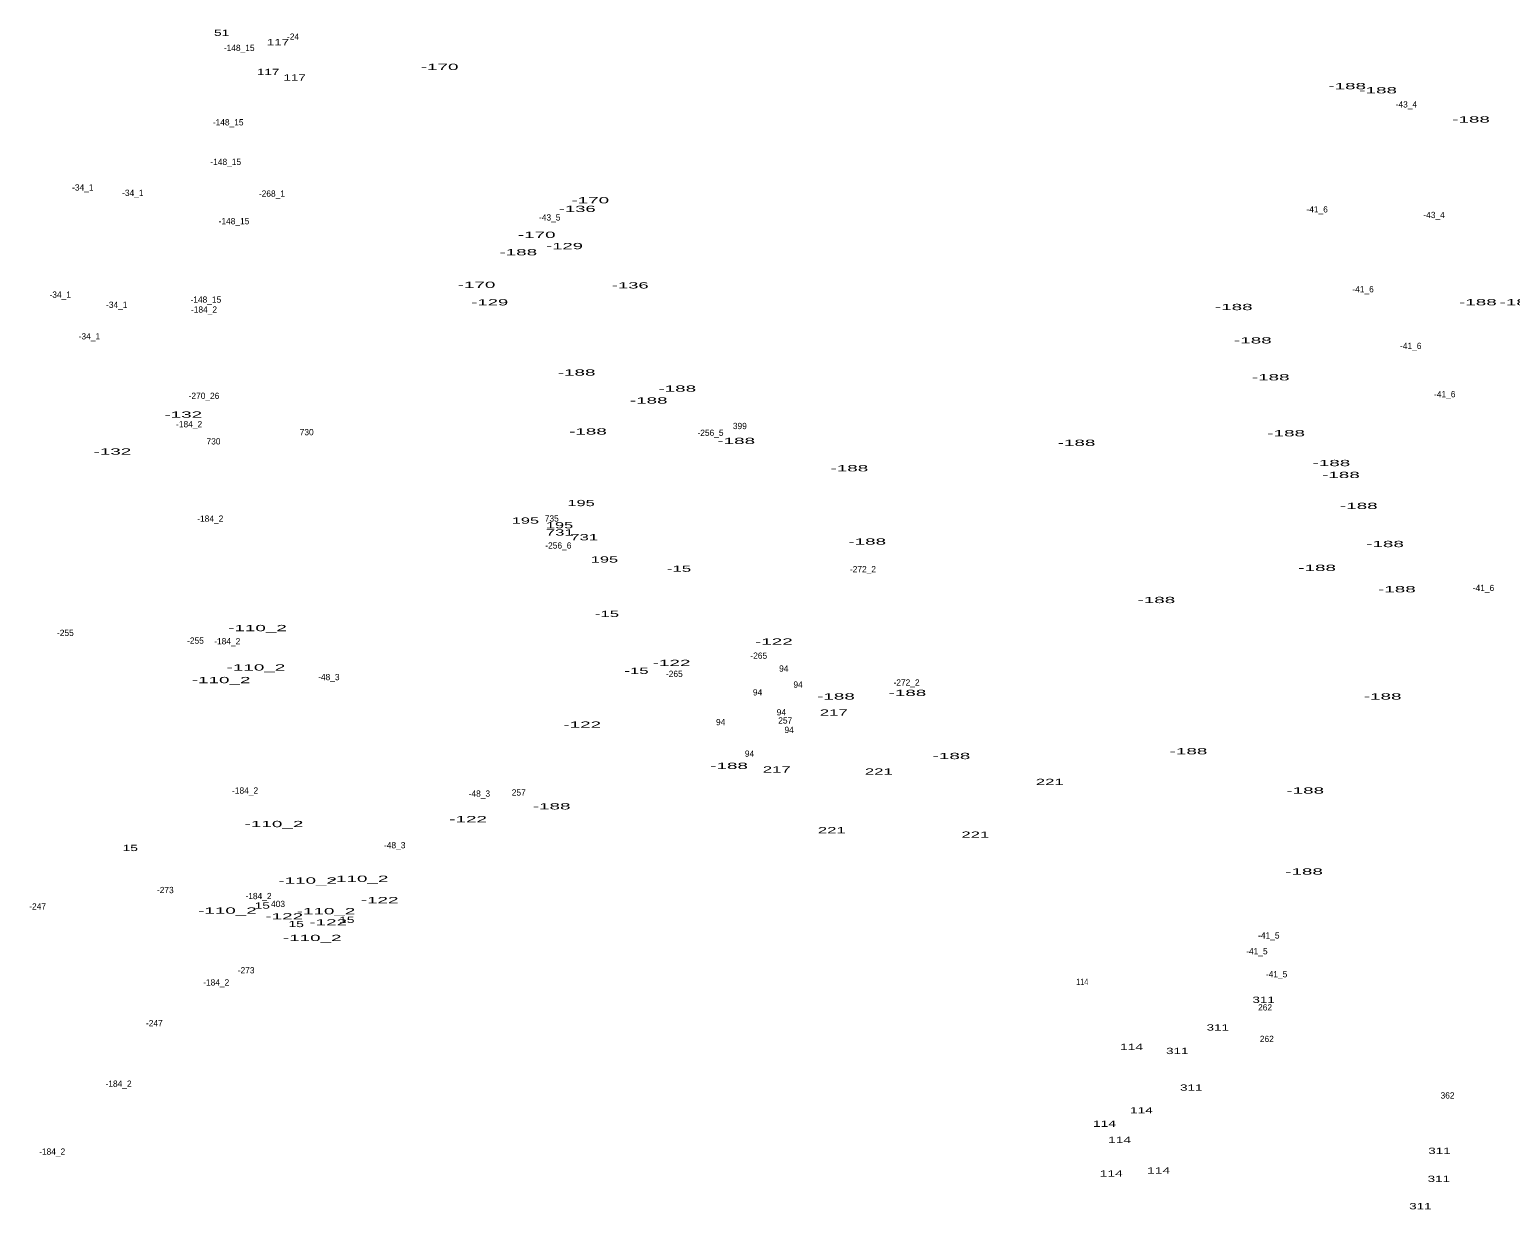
# Model space of a CAD drawing. Extents: x -658595 to -655205, y -1004347 to -1000147.
# Drawn here: x -657379 to -656433, y -1003735 to -1002981 of the extents above; entities that cross this region are included whole.
import ezdxf
from ezdxf.enums import TextEntityAlignment as Align

# ---------------------------------------------------------------- set-up
doc = ezdxf.new("R2010")
doc.units = 0
doc.header["$LTSCALE"] = 1.6
doc.layers.add('24', color=7, linetype='Continuous')

msp = doc.modelspace()

# ---------------------------------------------------------------- texts
at = {"layer": '24'}
for s, width, p in [('51', 1.65, (-657255.897, -1002984.88)), ('117', 1.6, (-657219.939, -1002990.92)), ('117', 1.6, (-657226.219, -1003009.94)), ('117', 1.6, (-657209.289, -1003013.46)), ('-170', 2.25, (-657116.701, -1003006.7)), ('-188', 2.25, (-656536.991, -1003018.98)), ('-188', 2.25, (-656517.211, -1003021.64)), ('-188', 2.25, (-656457.881, -1003040.28)), ('-136', 2.2, (-657028.795, -1003097.41)), ('-170', 2.25, (-657020.471, -1003091.93)), ('-170', 2.25, (-657054.701, -1003114)), ('-188', 2.25, (-657066.451, -1003125.14)), ('-129', 2.2, (-657036.925, -1003121.19)), ('-170', 2.25, (-657093.121, -1003145.96)), ('-136', 2.2, (-656994.945, -1003146.3)), ('-129', 2.2, (-657084.655, -1003157.14)), ('-188', 2.25, (-656609.451, -1003160.13)), ('-188', 2.25, (-656453.501, -1003157.09)), ('-188', 2.25, (-656427.631, -1003157.09)), ('-188', 2.25, (-656597.271, -1003181.44)), ('-188', 2.25, (-657029.181, -1003201.98)), ('-188', 2.25, (-656964.901, -1003212.25)), ('-188', 2.25, (-656585.861, -1003205.03)), ('-188', 2.25, (-656983.151, -1003219.86)), ('-132', 2.25, (-657280.441, -1003228.87)), ('-188', 2.25, (-657021.951, -1003239.65)), ('-188', 2.25, (-656575.971, -1003240.8)), ('-188', 2.25, (-656927.241, -1003245.69)), ('-188', 2.25, (-656709.861, -1003246.89)), ('-132', 2.25, (-657325.701, -1003252.46)), ('-188', 2.25, (-656547.071, -1003259.83)), ('-188', 2.25, (-656854.971, -1003263.19)), ('-188', 2.25, (-656540.981, -1003267.44)), ('195', 1.95, (-657026.323, -1003285.39)), ('-188', 2.25, (-656529.571, -1003287.22)), ('195', 1.95, (-657061.893, -1003296.61)), ('731', 2, (-657039.943, -1003304.19)), ('195', 1.95, (-657040.113, -1003299.56)), ('731', 2, (-657024.353, -1003307.24)), ('-188', 2.25, (-656843.561, -1003309.99)), ('-188', 2.25, (-656512.831, -1003311.57)), ('195', 1.95, (-657011.403, -1003321.44)), ('-15', 2, (-656963.771, -1003327.35)), ('-188', 2.25, (-656556.191, -1003326.79)), ('-188', 2.25, (-656505.231, -1003340.49)), ('-188', 2.25, (-656658.891, -1003347.34)), ('-15', 2, (-657009.791, -1003356.26)), ('-110_2', 2.25, (-657233.034, -1003365.28)), ('-122', 2.25, (-656903.171, -1003373.92)), ('-110_2', 2.25, (-657233.994, -1003390.44)), ('-122', 2.25, (-656968.531, -1003387.58)), ('-110_2', 2.25, (-657256.274, -1003398.51)), ('-15', 2, (-656990.961, -1003392.6)), ('-188', 2.25, (-656863.531, -1003408.98)), ('-188', 2.25, (-656817.881, -1003406.7)), ('-188', 2.25, (-656514.351, -1003408.98)), ('217', 2, (-656864.923, -1003419.27)), ('-122', 2.25, (-657025.621, -1003427)), ('-188', 2.25, (-656789.741, -1003447.03)), ('-188', 2.25, (-656638.351, -1003443.99)), ('-188', 2.25, (-656931.801, -1003453.32)), ('217', 2, (-656901.343, -1003455.61)), ('221', 2, (-656836.137, -1003456.97)), ('221', 2, (-656726.987, -1003463.63)), ('-188', 2.25, (-656563.801, -1003469.1)), ('-188', 2.25, (-657045.151, -1003479.19)), ('-110_2', 2.25, (-657222.484, -1003490.51)), ('-122', 2.25, (-657098.471, -1003487.38)), ('221', 2, (-656866.187, -1003494.45)), ('221', 2, (-656774.527, -1003497.3)), ('15', 1.65, (-657314.327, -1003505.81)), ('-188', 2.25, (-656564.561, -1003520.85)), ('-110_2', 2.25, (-657200.974, -1003526.62)), ('-110_2', 2.25, (-657168.144, -1003525.47)), ('15', 1.65, (-657229.997, -1003542.6)), ('-122', 2.25, (-657155.001, -1003539.11)), ('-110_2', 2.25, (-657252.244, -1003545.83)), ('-122', 2.25, (-657215.941, -1003549.49)), ('-110_2', 2.25, (-657189.254, -1003546.2)), ('15', 1.65, (-657175.987, -1003551.74)), ('15', 1.65, (-657208.317, -1003554.4)), ('-122', 2.25, (-657187.871, -1003553.34)), ('-110_2', 2.25, (-657198.094, -1003563.31)), ('114', 0.8, (-656706.199, -1003591.32)), ('311', 1.6, (-656590.374, -1003602.8)), ('311', 1.6, (-656619.664, -1003620.49)), ('114', 1.65, (-656674.729, -1003632.93)), ('311', 1.6, (-656645.534, -1003635.52)), ('311', 1.6, (-656636.594, -1003658.92)), ('114', 1.65, (-656668.459, -1003673.45)), ('114', 1.65, (-656692.039, -1003682.01)), ('114', 1.65, (-656682.339, -1003692.29)), ('311', 1.6, (-656478.074, -1003699.32)), ('114', 1.65, (-656687.669, -1003713.79)), ('114', 1.65, (-656657.429, -1003711.88)), ('311', 1.6, (-656478.454, -1003717.21)), ('311', 1.6, (-656490.244, -1003734.71))]:
    msp.add_text(s, height=4, dxfattribs=dict(at, width=width)).set_placement(p, align=Align.CENTER)
for s, p in [('-148_15', (-657244.713, -1002994.55)), ('-24', (-657210.329, -1002987.38)), ('-43_4', (-656499.201, -1003030.66)), ('-148_15', (-657251.753, -1003042.11)), ('-148_15', (-657253.293, -1003067.38)), ('-34_1', (-657344.59, -1003083.74)), ('-34_1', (-657312.65, -1003087.18)), ('-268_1', (-657223.812, -1003087.67)), ('-41_6', (-656556.176, -1003097.75)), ('-148_15', (-657248.043, -1003105.27)), ('-43_5', (-657046.367, -1003102.9)), ('-43_4', (-656481.491, -1003101.33)), ('-34_1', (-657359.04, -1003152.23)), ('-148_15', (-657266.013, -1003155.4)), ('-41_6', (-656526.856, -1003148.8)), ('-34_1', (-657322.91, -1003158.7)), ('-184_2', (-657267.19, -1003161.76)), ('-34_1', (-657340.41, -1003178.87)), ('-41_6', (-656496.386, -1003184.99)), ('-270_26', (-657267.196, -1003216.89)), ('-41_6', (-656474.676, -1003215.85)), ('-184_2', (-657276.7, -1003235)), ('730', (-657201.597, -1003240.08)), ('-256_5', (-656943.668, -1003240.49)), ('399', (-656924.938, -1003236.17)), ('730', (-657261.117, -1003245.98)), ('-184_2', (-657263.19, -1003295.37)), ('735', (-657045.063, -1003295.26)), ('-256_6', (-657040.863, -1003312.52)), ('-272_2', (-656846.278, -1003327.65)), ('-41_6', (-656449.926, -1003339.66)), ('-255', (-657355.745, -1003368.35)), ('-255', (-657272.635, -1003373.3)), ('-184_2', (-657252.35, -1003373.72)), ('-265', (-656912.84, -1003382.93)), ('94', (-656896.867, -1003391.14)), ('-48_3', (-657187.447, -1003396.6)), ('-265', (-656966.79, -1003394.55)), ('94', (-656887.747, -1003401.42)), ('-272_2', (-656818.438, -1003400.06)), ('94', (-656913.607, -1003406.36)), ('94', (-656898.397, -1003419.11)), ('94', (-656937.187, -1003425.39)), ('257', (-656895.933, -1003424.32)), ('94', (-656893.447, -1003430.33)), ('94', (-656918.747, -1003445.55)), ('-184_2', (-657240.94, -1003469.1)), ('-48_3', (-657091.297, -1003471.08)), ('257', (-657066.153, -1003470.35)), ('-48_3', (-657145.367, -1003504.03)), ('-273', (-657291.921, -1003532.69)), ('-247', (-657373.465, -1003543.16)), ('-184_2', (-657232.38, -1003536.53)), ('403', (-657219.905, -1003541.57)), ('-41_5', (-656587.05, -1003561.71)), ('-41_5', (-656594.67, -1003571.8)), ('-273', (-657240.281, -1003583.97)), ('-41_5', (-656582.1, -1003586.47)), ('-184_2', (-657259.39, -1003591.71)), ('262', (-656589.463, -1003607.66)), ('-247', (-657298.915, -1003617.74)), ('262', (-656588.323, -1003627.83)), ('-184_2', (-657321.77, -1003656.44)), ('362', (-656472.883, -1003663.93)), ('-184_2', (-657364.17, -1003699.81))]:
    msp.add_text(s, height=4, dxfattribs=at).set_placement(p, align=Align.CENTER)

doc.saveas('drawing.dxf')
